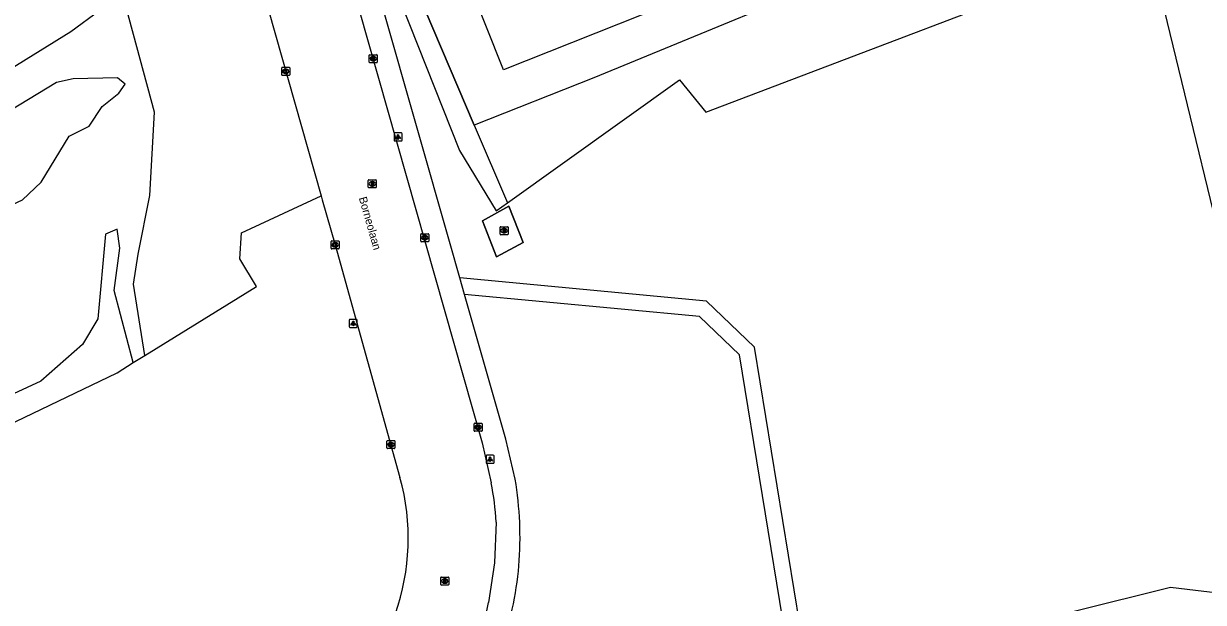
# Model space of a CAD drawing. Extents: x 162880 to 165536, y 384011 to 385179.
# Drawn here: x 163130.7 to 163278.2, y 384176 to 384248.3 of the extents above; entities that cross this region are included whole.
import ezdxf

# ---------------------------------------------------------------- set-up
doc = ezdxf.new("R2010")
doc.units = 0
for name, color, linetype in [('IMGEO_Groenvoorziening', 7, 'Continuous'), ('IMGEO_Hek', 7, 'Continuous'), ('IMGEO_Kolk', 7, 'Continuous'), ('IMGEO_Lichtpunt', 7, 'Continuous'), ('IMGEO_Loofbos', 7, 'Continuous'), ('IMGEO_Openbare_ruimte_label', 7, 'Continuous'), ('IMGEO_Parkeervlak_halfverhard', 7, 'Continuous'), ('IMGEO_Rijbaan_lokaal_gesloten', 7, 'Continuous'), ('IMGEO_Rijbaan_lokaal_open', 7, 'Continuous'), ('IMGEO_Rioolput', 7, 'Continuous'), ('IMGEO_Voetpad_open', 7, 'Continuous')]:
    doc.layers.add(name, color=color, linetype=linetype)

msp = doc.modelspace()

# ---------------------------------------------------------------- linework, layer by layer
at = {"layer": 'IMGEO_Groenvoorziening'}
for points in [[(163145.91, 384206.85), (163144.47, 384215.75), (163145.04, 384219.49), (163146.5, 384226.82), (163147.08, 384237.23), (163143.51, 384250.48), (163152.07, 384253.98), (163153.4, 384249.65), (163158.36, 384249.76), (163158.29, 384250), (163157.47, 384252.83)], [(163121.43, 384222.05), (163130.6, 384226.3), (163132.93, 384228.51), (163136.44, 384234.23), (163138.94, 384235.48), (163140.54, 384237.97), (163142.64, 384239.63), (163143.42, 384240.76), (163142.49, 384241.53), (163136.94, 384241.4), (163134.85, 384240.97), (163120.83, 384232.45), (163119.25, 384230.33), (163118.73, 384227.6), (163119.05, 384225.09), (163121.43, 384222.05)], [(163187.07, 384235.63), (163191.22, 384225.92)], [(163144.45, 384205.95), (163142.07, 384214.97), (163142.76, 384220.26), (163142.43, 384222.62), (163140.99, 384222.02), (163140.02, 384211.41), (163138.09, 384208.2), (163132.89, 384203.65), (163123.24, 384199.18), (163116.64, 384196.81), (163116.12, 384192.07)]]:
    msp.add_lwpolyline(points, dxfattribs=at)
at = {"layer": 'IMGEO_Hek'}
for points in [[(163168.13, 384279.9), (163168.27, 384279.57), (163180.92, 384250), (163187.07, 384235.63), (163191.22, 384225.92)], [(163188.1, 384223.66), (163191.4, 384225.49), (163193.16, 384220.95), (163189.84, 384219.16)], [(163189.84, 384219.16), (163188.1, 384223.66)]]:
    msp.add_lwpolyline(points, dxfattribs=at)
at = {"layer": 'IMGEO_Kolk'}
for p, q in [((163173.93, 384243.5), (163173.93, 384244.36)), ((163174.01, 384244.43), (163174.86, 384244.43)), ((163174.42, 384244.21), (163174.45, 384244.21)), ((163174.93, 384244.36), (163174.93, 384243.5)), ((163163, 384241.92), (163163, 384242.77)), ((163163.07, 384242.85), (163163.92, 384242.85)), ((163163.48, 384242.62), (163163.51, 384242.62)), ((163164, 384242.77), (163164, 384241.92)), ((163174.86, 384243.43), (163174.01, 384243.43)), ((163174.44, 384243.65), (163174.42, 384243.65)), ((163163.92, 384241.84), (163163.07, 384241.84)), ((163163.51, 384242.07), (163163.48, 384242.07)), ((163180.38, 384221.13), (163180.38, 384221.98)), ((163180.46, 384222.06), (163181.31, 384222.06)), ((163181.39, 384221.98), (163181.39, 384221.13)), ((163169.17, 384220.24), (163169.17, 384221.1)), ((163169.25, 384221.17), (163170.1, 384221.17)), ((163169.66, 384220.95), (163169.68, 384220.95)), ((163170.17, 384221.1), (163170.17, 384220.24)), ((163181.31, 384221.06), (163180.46, 384221.06)), ((163180.87, 384221.84), (163180.9, 384221.84)), ((163180.89, 384221.28), (163180.87, 384221.28)), ((163170.1, 384220.17), (163169.25, 384220.17)), ((163169.68, 384220.39), (163169.66, 384220.39)), ((163187.12, 384198.38), (163187.97, 384198.38)), ((163187.04, 384197.45), (163187.04, 384198.3)), ((163187.97, 384197.38), (163187.12, 384197.38)), ((163187.53, 384198.16), (163187.56, 384198.16)), ((163187.55, 384197.6), (163187.53, 384197.6)), ((163188.04, 384198.3), (163188.04, 384197.45)), ((163176.15, 384195.29), (163176.15, 384196.14)), ((163176.23, 384196.21), (163177.08, 384196.21)), ((163176.64, 384195.99), (163176.66, 384195.99)), ((163176.66, 384195.43), (163176.64, 384195.43)), ((163177.15, 384196.14), (163177.15, 384195.29)), ((163177.08, 384195.21), (163176.23, 384195.21))]:
    msp.add_line(p, q, dxfattribs=at)
for points in [[(163173.93, 384243.5), (163173.93, 384244.36)], [(163174.01, 384244.43), (163174.86, 384244.43)], [(163174.25, 384244.13), (163174.38, 384244.13), (163174.38, 384243.98), (163174.51, 384244.13), (163174.67, 384244.13), (163174.53, 384243.98), (163174.68, 384243.73), (163174.53, 384243.73), (163174.44, 384243.9), (163174.38, 384243.83), (163174.38, 384243.73), (163174.25, 384243.73), (163174.25, 384244.13)], [(163174.93, 384244.36), (163174.93, 384243.5)], [(163163, 384241.92), (163163, 384242.77)], [(163163.07, 384242.85), (163163.92, 384242.85)], [(163163.32, 384242.54), (163163.44, 384242.54), (163163.44, 384242.39), (163163.57, 384242.54), (163163.73, 384242.54), (163163.59, 384242.39), (163163.74, 384242.14), (163163.59, 384242.14), (163163.5, 384242.31), (163163.44, 384242.24), (163163.44, 384242.14), (163163.32, 384242.14), (163163.32, 384242.54)], [(163164, 384242.77), (163164, 384241.92)], [(163174.86, 384243.43), (163174.01, 384243.43)], [(163163.92, 384241.84), (163163.07, 384241.84)], [(163180.38, 384221.13), (163180.38, 384221.98)], [(163180.46, 384222.06), (163181.31, 384222.06)], [(163181.39, 384221.98), (163181.39, 384221.13)], [(163169.17, 384220.24), (163169.17, 384221.1)], [(163169.25, 384221.17), (163170.1, 384221.17)], [(163169.49, 384220.87), (163169.62, 384220.87), (163169.62, 384220.72), (163169.74, 384220.87), (163169.91, 384220.87), (163169.76, 384220.72), (163169.92, 384220.47), (163169.76, 384220.47), (163169.68, 384220.63), (163169.62, 384220.57), (163169.62, 384220.47), (163169.49, 384220.47), (163169.49, 384220.87)], [(163170.17, 384221.1), (163170.17, 384220.24)], [(163181.31, 384221.06), (163180.46, 384221.06)], [(163180.7, 384221.76), (163180.83, 384221.76), (163180.83, 384221.61), (163180.96, 384221.76), (163181.12, 384221.76), (163180.98, 384221.61), (163181.13, 384221.36), (163180.98, 384221.36), (163180.89, 384221.52), (163180.83, 384221.46), (163180.83, 384221.36), (163180.7, 384221.36), (163180.7, 384221.76)], [(163170.1, 384220.17), (163169.25, 384220.17)], [(163187.12, 384198.38), (163187.97, 384198.38)], [(163187.04, 384197.45), (163187.04, 384198.3)], [(163187.97, 384197.38), (163187.12, 384197.38)], [(163187.36, 384198.08), (163187.49, 384198.08), (163187.49, 384197.93), (163187.62, 384198.08), (163187.78, 384198.08), (163187.64, 384197.93), (163187.79, 384197.68), (163187.64, 384197.68), (163187.55, 384197.84), (163187.49, 384197.77), (163187.49, 384197.68), (163187.36, 384197.68), (163187.36, 384198.08)], [(163188.04, 384198.3), (163188.04, 384197.45)], [(163176.15, 384195.29), (163176.15, 384196.14)], [(163176.23, 384196.21), (163177.08, 384196.21)], [(163176.47, 384195.91), (163176.6, 384195.91), (163176.6, 384195.76), (163176.72, 384195.91), (163176.89, 384195.91), (163176.74, 384195.76), (163176.9, 384195.51), (163176.74, 384195.51), (163176.66, 384195.68), (163176.6, 384195.61), (163176.6, 384195.51), (163176.47, 384195.51), (163176.47, 384195.91)], [(163177.15, 384196.14), (163177.15, 384195.29)], [(163177.08, 384195.21), (163176.23, 384195.21)]]:
    msp.add_lwpolyline(points, dxfattribs=at)
for centre, start, end in [((163174.01, 384244.36), 91.552, 178.448), ((163174.01, 384244.36), 91.552, 178.448), ((163174.86, 384244.36), 1.552, 88.448), ((163174.86, 384244.36), 1.552, 88.448), ((163163.07, 384242.77), 91.552, 178.448), ((163163.07, 384242.77), 91.552, 178.448), ((163163.92, 384242.77), 1.552, 88.448), ((163163.92, 384242.77), 1.552, 88.448), ((163174.01, 384243.51), 181.552, 268.448), ((163174.01, 384243.51), 181.552, 268.448), ((163174.86, 384243.51), 271.552, 358.448), ((163174.86, 384243.51), 271.552, 358.448), ((163163.07, 384241.92), 181.552, 268.448), ((163163.07, 384241.92), 181.552, 268.448), ((163163.92, 384241.92), 271.552, 358.448), ((163163.92, 384241.92), 271.552, 358.448), ((163180.46, 384221.98), 91.552, 178.448), ((163180.46, 384221.98), 91.552, 178.448), ((163181.31, 384221.98), 1.552, 88.448), ((163181.31, 384221.98), 1.552, 88.448), ((163169.25, 384221.09), 91.552, 178.448), ((163169.25, 384221.09), 91.552, 178.448), ((163170.1, 384221.09), 1.552, 88.448), ((163170.1, 384221.09), 1.552, 88.448), ((163180.46, 384221.13), 181.552, 268.448), ((163180.46, 384221.13), 181.552, 268.448), ((163181.31, 384221.13), 271.552, 358.448), ((163181.31, 384221.13), 271.552, 358.448), ((163169.25, 384220.24), 181.552, 268.448), ((163169.25, 384220.24), 181.552, 268.448), ((163170.1, 384220.24), 271.552, 358.448), ((163170.1, 384220.24), 271.552, 358.448), ((163187.12, 384198.3), 91.552, 178.448), ((163187.12, 384198.3), 91.552, 178.448), ((163187.97, 384198.3), 1.552, 88.448), ((163187.97, 384198.3), 1.552, 88.448), ((163187.12, 384197.45), 181.552, 268.448), ((163187.12, 384197.45), 181.552, 268.448), ((163187.97, 384197.45), 271.552, 358.448), ((163187.97, 384197.45), 271.552, 358.448), ((163176.23, 384196.14), 91.552, 178.448), ((163176.23, 384196.14), 91.552, 178.448), ((163177.08, 384196.14), 1.552, 88.448), ((163177.08, 384196.14), 1.552, 88.448), ((163176.23, 384195.29), 181.552, 268.448), ((163176.23, 384195.29), 181.552, 268.448), ((163177.08, 384195.29), 271.552, 358.448), ((163177.08, 384195.29), 271.552, 358.448)]:
    msp.add_arc(centre, 0.0765, start, end, dxfattribs=at)
for centre, major_axis, ratio, start_param, end_param in [((163174.42, 384243.93), (-0.387, 0.002), 0.722429, 4.712389, 7.853982), ((163174.44, 384243.93), (-0.39, 0.002), 0.717154, 1.570796, 4.712389), ((163163.48, 384242.34), (-0.387, 0.002), 0.722429, 4.712389, 7.853982), ((163163.51, 384242.34), (-0.39, 0.002), 0.717154, 1.570796, 4.712389), ((163169.66, 384220.67), (-0.387, 0.002), 0.722429, 4.712389, 7.853982), ((163169.68, 384220.67), (-0.39, 0.002), 0.717154, 1.570796, 4.712389), ((163180.87, 384221.56), (-0.387, 0.002), 0.722429, 4.712389, 7.853982), ((163180.9, 384221.56), (-0.39, 0.002), 0.717154, 1.570796, 4.712389), ((163187.53, 384197.88), (-0.387, 0.002), 0.722429, 4.712389, 7.853982), ((163187.55, 384197.88), (-0.39, 0.002), 0.717154, 1.570796, 4.712389), ((163176.64, 384195.71), (-0.387, 0.002), 0.722429, 4.712389, 7.853982), ((163176.66, 384195.71), (-0.39, 0.002), 0.717154, 1.570796, 4.712389)]:
    msp.add_ellipse(centre, major_axis=major_axis, ratio=ratio, start_param=start_param, end_param=end_param, dxfattribs=at)
at = {"layer": 'IMGEO_Lichtpunt'}
for p, q in [((163177.04, 384234.55), (163177.04, 384233.74)), ((163177.04, 384234.55), (163177.04, 384233.74)), ((163177.95, 384234.65), (163177.14, 384234.65)), ((163177.95, 384234.65), (163177.14, 384234.65)), ((163178.04, 384233.74), (163178.04, 384234.55)), ((163178.04, 384233.74), (163178.04, 384234.55)), ((163177.14, 384233.65), (163177.95, 384233.65)), ((163177.14, 384233.65), (163177.95, 384233.65)), ((163171.44, 384211.26), (163171.44, 384210.45)), ((163171.44, 384211.26), (163171.44, 384210.45)), ((163172.34, 384211.35), (163171.53, 384211.35)), ((163172.34, 384211.35), (163171.53, 384211.35)), ((163171.53, 384210.35), (163172.34, 384210.35)), ((163171.53, 384210.35), (163172.34, 384210.35)), ((163172.44, 384210.45), (163172.44, 384211.26)), ((163172.44, 384210.45), (163172.44, 384211.26)), ((163188.53, 384194.29), (163188.53, 384193.48)), ((163188.53, 384194.29), (163188.53, 384193.48)), ((163189.44, 384194.38), (163188.63, 384194.38)), ((163189.44, 384194.38), (163188.63, 384194.38)), ((163189.53, 384193.48), (163189.53, 384194.29)), ((163189.53, 384193.48), (163189.53, 384194.29)), ((163188.63, 384193.38), (163189.44, 384193.38)), ((163188.63, 384193.38), (163189.44, 384193.38))]:
    msp.add_line(p, q, dxfattribs=at)
for points in [[(163177.42, 384234.21), (163177.46, 384234.19), (163177.27, 384233.92), (163177.23, 384233.95), (163177.42, 384234.21)], [(163177.52, 384234.17), (163177.57, 384234.17), (163177.57, 384233.84), (163177.52, 384233.84), (163177.52, 384234.17)], [(163177.63, 384234.19), (163177.67, 384234.21), (163177.86, 384233.95), (163177.82, 384233.92), (163177.63, 384234.19)], [(163171.81, 384210.92), (163171.85, 384210.89), (163171.66, 384210.63), (163171.63, 384210.66), (163171.81, 384210.92)], [(163171.91, 384210.87), (163171.96, 384210.87), (163171.96, 384210.55), (163171.91, 384210.55), (163171.91, 384210.87)], [(163172.02, 384210.89), (163172.06, 384210.92), (163172.25, 384210.66), (163172.21, 384210.63), (163172.02, 384210.89)], [(163188.91, 384193.95), (163188.95, 384193.92), (163188.76, 384193.66), (163188.72, 384193.69), (163188.91, 384193.95)], [(163189.01, 384193.9), (163189.06, 384193.9), (163189.06, 384193.58), (163189.01, 384193.58), (163189.01, 384193.9)], [(163189.12, 384193.92), (163189.16, 384193.95), (163189.34, 384193.69), (163189.31, 384193.66), (163189.12, 384193.92)]]:
    msp.add_lwpolyline(points, dxfattribs=at)
for centre in [(163177.54, 384234.35), (163171.94, 384211.05), (163189.03, 384194.08)]:
    msp.add_circle(centre, 0.0994, dxfattribs=at)
for centre, start, end in [((163177.14, 384234.55), 90, 180), ((163177.14, 384234.55), 90, 180), ((163177.14, 384233.74), 180, 270), ((163177.14, 384233.74), 180, 270), ((163177.95, 384234.55), 0, 90), ((163177.95, 384234.55), 0, 90), ((163177.95, 384233.74), 270, 0), ((163177.95, 384233.74), 270, 360), ((163171.53, 384211.26), 90, 180), ((163171.53, 384211.26), 90, 180), ((163171.53, 384210.45), 180, 270), ((163171.53, 384210.45), 180, 270), ((163172.34, 384211.26), 0, 90), ((163172.34, 384211.26), 0, 90), ((163172.34, 384210.45), 270, 0), ((163172.34, 384210.45), 270, 360), ((163188.63, 384194.29), 90, 180), ((163188.63, 384194.29), 90, 180), ((163189.44, 384194.29), 0, 90), ((163189.44, 384194.29), 0, 90), ((163188.63, 384193.48), 180, 270), ((163188.63, 384193.48), 180, 270), ((163189.44, 384193.48), 270, 0), ((163189.44, 384193.48), 270, 360)]:
    msp.add_arc(centre, 0.0946, start, end, dxfattribs=at)
at = {"layer": 'IMGEO_Loofbos'}
for points in [[(163168.27, 384279.57), (163168.13, 384279.9), (163167.79, 384279.06), (163167.58, 384276.89), (163185.21, 384232.45), (163189.81, 384224.92), (163191.22, 384225.92)], [(163114.5, 384233.62), (163136.64, 384247.33), (163140.26, 384250), (163143.86, 384252.65), (163155.93, 384258.13)], [(163191.22, 384225.92), (163212.73, 384241.29), (163216, 384237.23), (163271.3, 384258.29), (163271.78, 384256.3), (163273.3, 384250), (163282.67, 384211.41), (163288.87, 384186.29), (163289.08, 384185.84)], [(163145.91, 384206.85), (163159.83, 384215.45), (163157.75, 384218.93), (163157.97, 384222.16), (163167.93, 384226.8)], [(163189.84, 384219.16), (163193.16, 384220.95), (163191.4, 384225.49), (163188.1, 384223.66), (163189.84, 384219.16)], [(163422.41, 384196.91), (163406.21, 384194.3), (163300.15, 384174.73), (163274.09, 384177.84), (163238.64, 384169.03), (163227.76, 384173.24), (163222.07, 384207.9), (163216.08, 384213.63), (163185.27, 384216.54)], [(163188.96, 384166.62), (163217.96, 384163.97), (163235.25, 384168.2), (163225.97, 384171.79), (163220.2, 384206.92), (163215.2, 384211.71), (163185.86, 384214.48)], [(163116.12, 384192.07), (163142.42, 384204.69), (163144.45, 384205.95)], [(163144.45, 384205.95), (163145.91, 384206.85)]]:
    msp.add_lwpolyline(points, dxfattribs=at)
at = {"layer": 'IMGEO_Parkeervlak_halfverhard'}
for points in [[(163258.41, 384315.44), (163275.73, 384271.9), (163202.02, 384241.53), (163187.07, 384235.63)], [(163187.07, 384235.63), (163180.92, 384250), (163168.27, 384279.57)]]:
    msp.add_lwpolyline(points, dxfattribs=at)
at = {"layer": 'IMGEO_Rijbaan_lokaal_gesloten'}
msp.add_lwpolyline([(163181.14, 384284.65), (163182.9, 384280.22), (163259.65, 384310.77), (163273.68, 384275.53), (163190.73, 384242.52), (163174.94, 384282.2)], dxfattribs=at)
at = {"layer": 'IMGEO_Rijbaan_lokaal_open'}
for points in [[(163164.54, 384278.41), (163165.22, 384276.03), (163168.3, 384265.42), (163172.66, 384250), (163188.06, 384195.92), (163189.17, 384190.92)], [(163160.32, 384253.65), (163161.35, 384250), (163167.93, 384226.8)], [(163167.93, 384226.8), (163168.07, 384226.31), (163169.67, 384220.66), (163177.77, 384191.62)], [(163189.79, 384186.04), (163189.6, 384180.94), (163188.83, 384176)]]:
    msp.add_lwpolyline(points, dxfattribs=at)
for centre, radius, start, end in [((163150.47, 384184.02), 28.34, 305.7253, 15.5526), ((163161.65, 384184.97), 28.15, 2.1703, 12.2039), ((163165.31, 384180.11), 23.88, 337.728, 350.0904)]:
    msp.add_arc(centre, radius, start, end, dxfattribs=at)
at = {"layer": 'IMGEO_Rioolput'}
for p, q in [((163173.82, 384227.87), (163173.82, 384228.72)), ((163173.89, 384228.8), (163174.75, 384228.8)), ((163174.31, 384228.57), (163174.33, 384228.57)), ((163174.33, 384228.02), (163174.31, 384228.02)), ((163174.82, 384228.72), (163174.82, 384227.87)), ((163174.75, 384227.79), (163173.89, 384227.79)), ((163190.29, 384222.01), (163190.29, 384222.86)), ((163190.37, 384222.94), (163191.22, 384222.94)), ((163191.22, 384221.94), (163190.37, 384221.94)), ((163190.78, 384222.72), (163190.8, 384222.72)), ((163190.8, 384222.16), (163190.78, 384222.16)), ((163191.29, 384222.86), (163191.29, 384222.01)), ((163182.95, 384179.16), (163183.81, 384179.16)), ((163182.88, 384178.23), (163182.88, 384179.09)), ((163183.81, 384178.16), (163182.95, 384178.16)), ((163183.39, 384178.38), (163183.36, 384178.38)), ((163183.37, 384178.94), (163183.39, 384178.94)), ((163183.88, 384179.09), (163183.88, 384178.23))]:
    msp.add_line(p, q, dxfattribs=at)
for points in [[(163173.82, 384227.87), (163173.82, 384228.72)], [(163173.89, 384228.8), (163174.75, 384228.8)], [(163174.41, 384228.49), (163174.16, 384228.49), (163174.16, 384228.09)], [(163174.16, 384228.09), (163174.28, 384228.09), (163174.28, 384228.26), (163174.29, 384228.26)], [(163174.34, 384228.41), (163174.28, 384228.41), (163174.28, 384228.33)], [(163174.28, 384228.33), (163174.33, 384228.33)], [(163174.34, 384228.23), (163174.41, 384228.09), (163174.55, 384228.09), (163174.48, 384228.22)], [(163174.82, 384228.72), (163174.82, 384227.87)], [(163174.75, 384227.79), (163173.89, 384227.79)], [(163190.29, 384222.01), (163190.29, 384222.86)], [(163190.37, 384222.94), (163191.22, 384222.94)], [(163191.22, 384221.94), (163190.37, 384221.94)], [(163190.88, 384222.63), (163190.63, 384222.64), (163190.63, 384222.24)], [(163190.63, 384222.24), (163190.75, 384222.24), (163190.75, 384222.4), (163190.76, 384222.4)], [(163190.81, 384222.56), (163190.75, 384222.56), (163190.75, 384222.47)], [(163190.75, 384222.47), (163190.8, 384222.47)], [(163190.81, 384222.37), (163190.88, 384222.24), (163191.02, 384222.24), (163190.96, 384222.36)], [(163191.29, 384222.86), (163191.29, 384222.01)], [(163182.95, 384179.16), (163183.81, 384179.16)], [(163182.88, 384178.23), (163182.88, 384179.09)], [(163183.81, 384178.16), (163182.95, 384178.16)], [(163183.47, 384178.86), (163183.21, 384178.86), (163183.21, 384178.46)], [(163183.21, 384178.46), (163183.34, 384178.46), (163183.34, 384178.62), (163183.35, 384178.62)], [(163183.39, 384178.78), (163183.34, 384178.78), (163183.34, 384178.7)], [(163183.34, 384178.7), (163183.39, 384178.7)], [(163183.4, 384178.59), (163183.47, 384178.46), (163183.61, 384178.46), (163183.54, 384178.59)], [(163183.88, 384179.09), (163183.88, 384178.23)]]:
    msp.add_lwpolyline(points, dxfattribs=at)
for centre, radius, start, end in [((163173.9, 384228.72), 0.0765, 91.552, 178.448), ((163173.9, 384228.72), 0.0765, 91.552, 178.448), ((163173.9, 384227.87), 0.0765, 181.552, 268.448), ((163173.9, 384227.87), 0.0765, 181.552, 268.448), ((163174.29, 384228.2), 0.0533, 26.0293, 88.6989), ((163174.32, 384228.52), 0.19, 274.7715, 282.9687), ((163174.34, 384228.32), 0.0964, 77.0061, 93.1865), ((163174.36, 384228.37), 0.0378, 276.6634, 79.6772), ((163174.41, 384228.38), 0.109, 350.3612, 89.416), ((163174.41, 384228.38), 0.112, 277.5842, 350.9817), ((163174.39, 384228.17), 0.108, 29.5134, 73.7905), ((163174.74, 384228.72), 0.0765, 1.552, 88.448), ((163174.74, 384228.72), 0.0765, 1.552, 88.448), ((163174.74, 384227.87), 0.0765, 271.552, 358.448), ((163174.74, 384227.87), 0.0765, 271.552, 358.448), ((163190.37, 384222.86), 0.0765, 91.552, 178.448), ((163190.37, 384222.86), 0.0765, 91.552, 178.448), ((163190.37, 384222.01), 0.0765, 181.552, 268.448), ((163190.37, 384222.01), 0.0765, 181.552, 268.448), ((163190.76, 384222.35), 0.0533, 26.0293, 88.6989), ((163190.79, 384222.66), 0.19, 274.7715, 282.9687), ((163190.81, 384222.46), 0.0964, 77.0061, 93.1865), ((163190.83, 384222.52), 0.0378, 276.6634, 79.6772), ((163190.88, 384222.53), 0.109, 350.3612, 89.416), ((163190.88, 384222.52), 0.112, 277.5842, 350.9817), ((163190.86, 384222.31), 0.108, 29.5134, 73.7905), ((163191.22, 384222.86), 0.0765, 1.552, 88.448), ((163191.22, 384222.86), 0.0765, 1.552, 88.448), ((163191.22, 384222.01), 0.0765, 271.552, 358.448), ((163191.22, 384222.01), 0.0765, 271.552, 358.448), ((163182.95, 384179.08), 0.0765, 91.552, 178.448), ((163182.95, 384179.08), 0.0765, 91.552, 178.448), ((163183.8, 384179.08), 0.0765, 1.552, 88.448), ((163183.8, 384179.08), 0.0765, 1.552, 88.448), ((163182.95, 384178.24), 0.0765, 181.552, 268.448), ((163182.95, 384178.24), 0.0765, 181.552, 268.448), ((163183.35, 384178.57), 0.0533, 26.0293, 88.6989), ((163183.4, 384178.68), 0.0964, 77.0061, 93.1865), ((163183.38, 384178.89), 0.19, 274.7715, 282.9687), ((163183.41, 384178.74), 0.0378, 276.6634, 79.6772), ((163183.47, 384178.75), 0.109, 350.3612, 89.416), ((163183.46, 384178.75), 0.112, 277.5842, 350.9817), ((163183.45, 384178.53), 0.108, 29.5134, 73.7905), ((163183.8, 384178.24), 0.0765, 271.552, 358.448), ((163183.8, 384178.24), 0.0765, 271.552, 358.448)]:
    msp.add_arc(centre, radius, start, end, dxfattribs=at)
for centre, major_axis, ratio, start_param, end_param in [((163174.31, 384228.29), (-0.387, 0.002), 0.722429, 4.712389, 7.853982), ((163174.33, 384228.29), (-0.39, 0.002), 0.717154, 1.570796, 4.712389), ((163190.78, 384222.44), (-0.387, 0.002), 0.722429, 4.712389, 7.853982), ((163190.8, 384222.44), (-0.39, 0.002), 0.717154, 1.570796, 4.712389), ((163183.37, 384178.66), (-0.387, 0.002), 0.722429, 4.712389, 7.853982), ((163183.39, 384178.66), (-0.39, 0.002), 0.717154, 1.570796, 4.712389)]:
    msp.add_ellipse(centre, major_axis=major_axis, ratio=ratio, start_param=start_param, end_param=end_param, dxfattribs=at)
at = {"layer": 'IMGEO_Voetpad_open'}
for points in [[(163185.27, 384216.54), (163184.05, 384220.8), (163175.71, 384250), (163172.67, 384261.11), (163171.41, 384260.66), (163165.81, 384280.3), (163163.27, 384289.2)], [(163185.86, 384214.48), (163185.27, 384216.54)], [(163192.18, 384191.4), (163191.02, 384196.41), (163185.86, 384214.48)]]:
    msp.add_lwpolyline(points, dxfattribs=at)
for centre, radius, start, end in [((163148.68, 384184.13), 44.1, 355.375, 9.4823), ((163148.52, 384184.49), 44.29, 340.7701, 354.9283)]:
    msp.add_arc(centre, radius, start, end, dxfattribs=at)

# ---------------------------------------------------------------- texts
at = {"layer": 'IMGEO_Openbare_ruimte_label'}
msp.add_text('Borneolaan', height=1, rotation=285.8982, dxfattribs=at).set_placement((163172.63, 384226.52))

doc.saveas('drawing.dxf')
